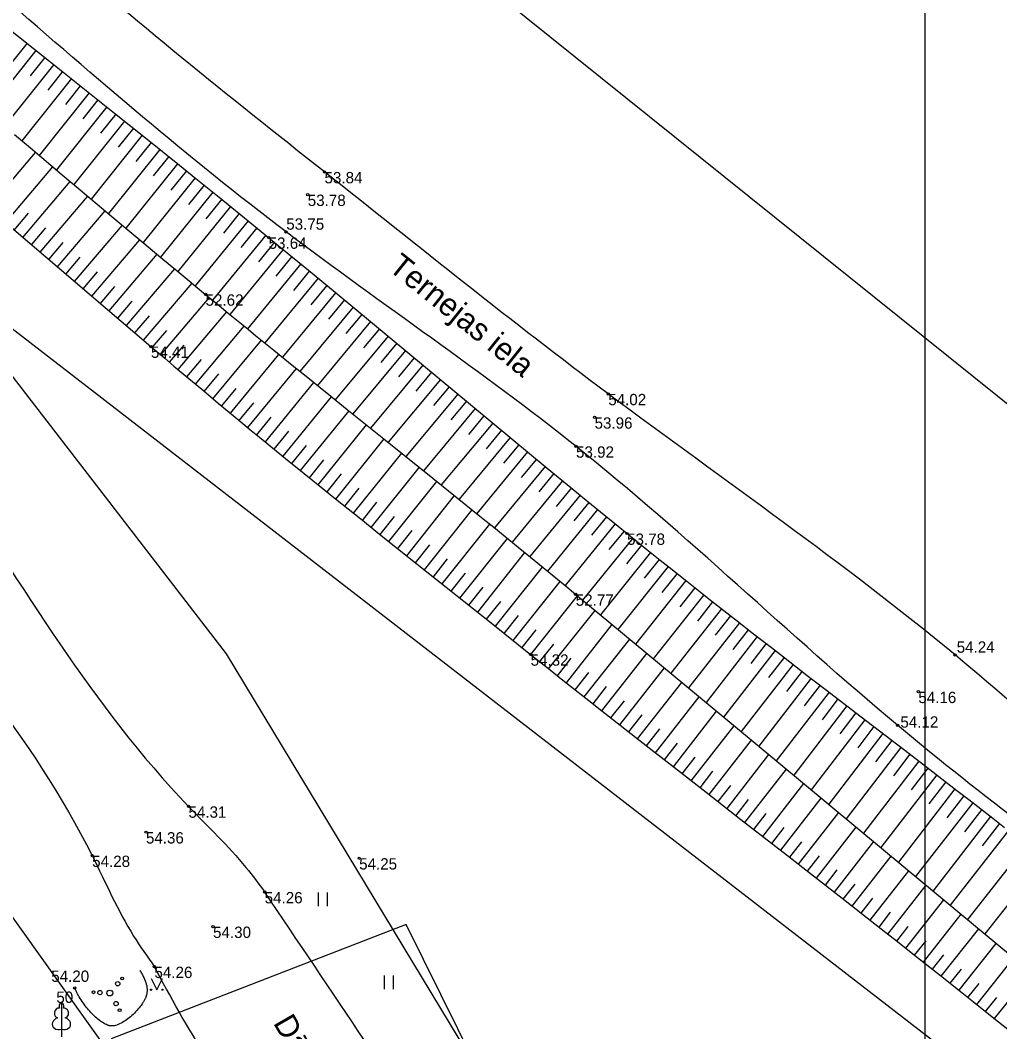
# Model space of a CAD drawing. Extents: x 578395 to 578590, y 418519 to 418816.
# Drawn here: x 578460.43 to 578503.64, y 418601.62 to 418646.22 of the extents above; entities that cross this region are included whole.
import ezdxf

# ---------------------------------------------------------------- set-up
doc = ezdxf.new("R2010")
doc.units = 0
for name, color, linetype in [('CELI_CMAL_####_####_#', 7, 'Continuous'), ('CELI_IELA_####_TKST_#', 7, 'Continuous'), ('ELEK_VADP_ZSPR_####_#', 7, 'Continuous'), ('RAMI_PLAN_####_TKST_#', 7, 'Continuous'), ('RELJ_AATZ_####_TKST_#', 7, 'Continuous'), ('RELJ_ELEM_####_####_#', 7, 'Continuous'), ('RELJ_NOGA_####_####_#', 7, 'Continuous'), ('RELJ_NOGL_####_####_#', 7, 'Continuous'), ('ROBZ_PROJ_####_####_#', 7, 'Continuous'), ('ROBZ_UZMR_####_####_#', 7, 'Continuous'), ('TERT_DIAM_####_TKST_#', 7, 'Continuous'), ('TERT_ELEM_####_####_#', 7, 'Continuous'), ('TERT_KONT_####_####_#', 7, 'Continuous')]:
    doc.layers.add(name, color=color, linetype=linetype)

msp = doc.modelspace()

# ---------------------------------------------------------------- linework, layer by layer
at = {"layer": 'CELI_CMAL_####_####_#'}
for points in [[(578540.02, 418586.371), (578525.988, 418597.847), (578512.594, 418608.642), (578501.669, 418618.235), (578486.368, 418629.744), (578473.85, 418639.529), (578461.404, 418649.849), (578445.482, 418664.308), (578434.891, 418671.618), (578433.593, 418673.245), (578433.709, 418674.571), (578434.344, 418682.513), (578433.832, 418698.668), (578431.508, 418715.146), (578429.961, 418730.384), (578428.634, 418741.31), (578426.857, 418755.172), (578424.464, 418771.373), (578422.35, 418787.381), (578420.601, 418802.682)], [(578422.643, 418673.344), (578426.408, 418667.598), (578432.023, 418657.972), (578440.378, 418642.229), (578453.358, 418623.699), (578463.599, 418609.382), (578465.428, 418605.837), (578466.347, 418604.486)], [(578433.603, 418667.727), (578433.533, 418667.219), (578433.834, 418664.827), (578435.716, 418660.389), (578444.472, 418644.493), (578457.112, 418626.41), (578467.85, 418611.554), (578470.384, 418608.861), (578471.211, 418607.779)], [(578538.092, 418583.58), (578523.866, 418595.463), (578510.65, 418606.122), (578499.131, 418615.129), (578484.947, 418627.43), (578472.156, 418636.888), (578459.663, 418647.262), (578443.345, 418661.302), (578436.955, 418666.057), (578434.564, 418667.369), (578433.603, 418667.727)], [(578494.854, 418568.017), (578493.222, 418570.924), (578490.763, 418575.52), (578488.331, 418580.13), (578485.806, 418584.688), (578479.899, 418594.609), (578471.211, 418607.779)], [(578473.294, 418588.796), (578474.34, 418590.351), (578474.316, 418591.662), (578471.816, 418595.464), (578470.23, 418598.144), (578468.612, 418600.561), (578466.347, 418604.486)]]:
    msp.add_spline(points, degree=3, dxfattribs=at)
at = {"layer": 'ELEK_VADP_ZSPR_####_#'}
msp.add_lwpolyline([(578485.065, 418590.965), (578477.452, 418606.345), (578464.439, 418601.302)], dxfattribs=at)
at = {"layer": 'RAMI_PLAN_####_TKST_#'}
msp.add_line((578500.351, 418519.111), (578500.351, 418667.611), dxfattribs=at)
at = {"layer": 'RELJ_ELEM_####_####_#'}
for centre in [(578473.85, 418639.529), (578473.111, 418638.53), (578472.156, 418636.888), (578471.386, 418636.641), (578468.603, 418634.132), (578466.192, 418631.832), (578486.368, 418629.744), (578485.765, 418628.71), (578484.947, 418627.43), (578487.2, 418623.587), (578484.935, 418620.902), (578482.943, 418618.258), (578501.669, 418618.235), (578500.049, 418616.61), (578499.131, 418615.129), (578467.85, 418611.554), (578465.971, 418610.418), (578463.599, 418609.382), (578475.378, 418609.27), (578471.211, 418607.779), (578468.934, 418606.253), (578466.347, 418604.486), (578462.833, 418603.546)]:
    msp.add_circle(centre, 0.05, dxfattribs=at)
at = {"layer": 'RELJ_NOGA_####_####_#'}
for p, q in [((578461.12, 418644.892), (578458.975, 418642.204)), ((578460.73, 418645.204), (578460.089, 418644.401)), ((578461.511, 418644.579), (578460.864, 418643.77)), ((578461.902, 418644.268), (578459.737, 418641.556)), ((578462.293, 418643.956), (578461.64, 418643.138)), ((578462.683, 418643.644), (578460.5, 418640.908)), ((578463.074, 418643.332), (578462.416, 418642.508)), ((578463.465, 418643.02), (578461.264, 418640.262)), ((578463.856, 418642.708), (578463.193, 418641.877)), ((578464.247, 418642.396), (578462.028, 418639.617)), ((578465.028, 418641.772), (578462.79, 418638.975)), ((578464.637, 418642.084), (578463.968, 418641.248)), ((578465.418, 418641.459), (578464.745, 418640.618)), ((578465.809, 418641.147), (578463.557, 418638.332)), ((578466.199, 418640.834), (578465.52, 418639.988)), ((578459.018, 418637.942), (578461.106, 418640.395)), ((578466.589, 418640.521), (578464.319, 418637.693)), ((578466.979, 418640.208), (578466.296, 418639.358)), ((578459.779, 418637.294), (578461.871, 418639.75)), ((578467.369, 418639.895), (578465.087, 418637.052)), ((578467.758, 418639.582), (578467.071, 418638.728)), ((578460.54, 418636.646), (578462.635, 418639.105)), ((578468.148, 418639.268), (578465.85, 418636.415)), ((578468.926, 418638.64), (578466.615, 418635.779)), ((578468.537, 418638.954), (578467.845, 418638.098)), ((578461.302, 418635.997), (578463.401, 418638.462)), ((578469.314, 418638.326), (578468.619, 418637.467)), ((578460.16, 418636.97), (578460.788, 418637.707)), ((578462.063, 418635.349), (578464.168, 418637.82)), ((578469.703, 418638.011), (578467.377, 418635.146)), ((578470.479, 418637.38), (578468.142, 418634.514)), ((578470.091, 418637.696), (578469.393, 418636.835)), ((578460.921, 418636.321), (578461.55, 418637.06)), ((578462.824, 418634.7), (578464.935, 418637.179)), ((578470.867, 418637.065), (578470.165, 418636.204)), ((578461.682, 418635.673), (578462.313, 418636.413)), ((578463.585, 418634.052), (578465.703, 418636.538)), ((578471.254, 418636.749), (578468.913, 418633.877)), ((578471.641, 418636.432), (578470.937, 418635.572)), ((578472.028, 418636.115), (578469.674, 418633.251)), ((578462.444, 418635.025), (578463.076, 418635.767)), ((578464.347, 418633.404), (578466.472, 418635.898)), ((578472.801, 418635.48), (578470.448, 418632.617)), ((578472.414, 418635.798), (578471.708, 418634.939)), ((578463.205, 418634.376), (578463.839, 418635.121)), ((578465.108, 418632.755), (578467.241, 418635.259)), ((578473.187, 418635.163), (578472.48, 418634.306)), ((578465.869, 418632.107), (578468.011, 418634.622)), ((578473.573, 418634.845), (578471.218, 418631.991)), ((578463.966, 418633.728), (578464.602, 418634.475)), ((578474.344, 418634.208), (578471.991, 418631.364)), ((578473.958, 418634.527), (578473.253, 418633.671)), ((578464.727, 418633.079), (578465.366, 418633.829)), ((578466.631, 418631.459), (578468.778, 418633.988)), ((578474.729, 418633.89), (578474.024, 418633.038)), ((578467.395, 418630.814), (578469.537, 418633.363)), ((578475.114, 418633.571), (578472.765, 418630.738)), ((578475.499, 418633.252), (578474.796, 418632.403)), ((578465.489, 418632.431), (578466.13, 418633.184)), ((578475.884, 418632.933), (578473.544, 418630.111)), ((578466.25, 418631.783), (578466.893, 418632.54)), ((578468.161, 418630.171), (578470.304, 418632.735)), ((578476.269, 418632.613), (578475.568, 418631.768)), ((578468.93, 418629.531), (578471.073, 418632.109)), ((578476.654, 418632.294), (578474.323, 418629.484)), ((578477.039, 418631.975), (578476.34, 418631.134)), ((578467.013, 418631.136), (578467.656, 418631.898)), ((578469.7, 418628.893), (578471.841, 418631.485)), ((578477.423, 418631.655), (578475.1, 418628.86)), ((578467.778, 418630.492), (578468.422, 418631.258)), ((578478.192, 418631.016), (578475.881, 418628.234)), ((578477.808, 418631.336), (578477.113, 418630.499)), ((578468.545, 418629.851), (578469.187, 418630.623)), ((578470.471, 418628.257), (578472.612, 418630.862)), ((578478.577, 418630.697), (578477.885, 418629.864)), ((578471.245, 418627.624), (578473.382, 418630.241)), ((578478.961, 418630.377), (578476.661, 418627.608)), ((578469.314, 418629.211), (578469.956, 418629.988)), ((578479.731, 418629.738), (578477.441, 418626.983)), ((578479.346, 418630.057), (578478.657, 418629.229)), ((578470.085, 418628.575), (578470.727, 418629.355)), ((578472.02, 418626.992), (578474.157, 418629.617)), ((578480.115, 418629.418), (578479.43, 418628.594)), ((578472.797, 418626.362), (578474.932, 418628.995)), ((578480.5, 418629.099), (578478.223, 418626.355)), ((578470.858, 418627.94), (578471.5, 418628.723)), ((578473.575, 418625.733), (578475.707, 418628.374)), ((578481.269, 418628.46), (578479.003, 418625.729)), ((578480.885, 418628.78), (578480.203, 418627.958)), ((578471.632, 418627.307), (578472.274, 418628.093)), ((578481.654, 418628.141), (578480.977, 418627.323)), ((578472.408, 418626.677), (578473.048, 418627.466)), ((578474.353, 418625.106), (578476.479, 418627.755)), ((578482.04, 418627.823), (578479.786, 418625.1)), ((578482.425, 418627.504), (578481.75, 418626.688)), ((578475.133, 418624.48), (578477.259, 418627.129)), ((578482.81, 418627.185), (578480.564, 418624.472)), ((578473.185, 418626.047), (578473.825, 418626.839)), ((578483.196, 418626.867), (578482.524, 418626.053)), ((578473.964, 418625.419), (578474.602, 418626.213)), ((578475.914, 418623.855), (578478.035, 418626.507)), ((578483.581, 418626.548), (578481.346, 418623.84)), ((578483.967, 418626.231), (578483.299, 418625.418)), ((578476.695, 418623.231), (578478.811, 418625.884)), ((578484.353, 418625.913), (578482.126, 418623.206)), ((578474.743, 418624.793), (578475.381, 418625.588)), ((578477.477, 418622.607), (578479.59, 418625.257)), ((578485.126, 418625.278), (578482.906, 418622.571)), ((578484.74, 418625.595), (578484.073, 418624.783)), ((578475.523, 418624.167), (578476.16, 418624.963)), ((578485.513, 418624.962), (578484.848, 418624.149)), ((578476.304, 418623.543), (578476.939, 418624.339)), ((578478.259, 418621.984), (578480.365, 418624.632)), ((578485.9, 418624.645), (578483.683, 418621.934)), ((578486.288, 418624.329), (578485.624, 418623.514)), ((578479.042, 418621.362), (578481.143, 418624.004)), ((578486.675, 418624.013), (578484.46, 418621.294)), ((578477.086, 418622.919), (578477.72, 418623.715)), ((578487.063, 418623.698), (578486.399, 418622.88)), ((578477.868, 418622.296), (578478.501, 418623.09)), ((578479.825, 418620.74), (578481.92, 418623.374)), ((578487.452, 418623.383), (578485.238, 418620.651)), ((578487.841, 418623.069), (578487.177, 418622.246)), ((578480.607, 418620.117), (578482.695, 418622.743)), ((578488.23, 418622.756), (578486.021, 418620.002)), ((578478.651, 418621.673), (578479.282, 418622.467)), ((578481.39, 418619.495), (578483.471, 418622.108)), ((578489.011, 418622.131), (578486.797, 418619.359)), ((578488.62, 418622.443), (578487.956, 418621.615)), ((578479.433, 418621.051), (578480.063, 418621.842)), ((578489.402, 418621.819), (578488.738, 418620.984)), ((578480.216, 418620.428), (578480.844, 418621.217)), ((578482.172, 418618.872), (578484.244, 418621.473)), ((578489.794, 418621.508), (578487.573, 418618.715)), ((578482.955, 418618.249), (578485.014, 418620.837)), ((578490.578, 418620.888), (578488.355, 418618.067)), ((578490.186, 418621.198), (578489.52, 418620.356)), ((578480.999, 418619.806), (578481.624, 418620.592)), ((578490.971, 418620.579), (578490.303, 418619.728)), ((578481.781, 418619.183), (578482.404, 418619.965)), ((578483.737, 418617.626), (578485.784, 418620.198)), ((578491.365, 418620.27), (578489.13, 418617.424)), ((578491.758, 418619.962), (578491.087, 418619.104)), ((578484.521, 418617.005), (578486.545, 418619.568)), ((578492.152, 418619.654), (578489.91, 418616.777)), ((578482.563, 418618.56), (578483.183, 418619.339)), ((578492.941, 418619.04), (578490.685, 418616.134)), ((578492.547, 418619.347), (578491.871, 418618.48)), ((578483.346, 418617.937), (578483.962, 418618.711)), ((578485.305, 418616.385), (578487.315, 418618.929)), ((578493.336, 418618.733), (578492.656, 418617.858)), ((578484.129, 418617.315), (578484.739, 418618.086)), ((578486.091, 418615.766), (578488.077, 418618.297)), ((578493.731, 418618.427), (578491.459, 418615.492)), ((578494.127, 418618.121), (578493.443, 418617.235)), ((578486.878, 418615.149), (578488.847, 418617.659)), ((578494.522, 418617.815), (578492.233, 418614.85)), ((578484.913, 418616.695), (578485.518, 418617.461)), ((578495.314, 418617.204), (578493.007, 418614.208)), ((578494.918, 418617.51), (578494.228, 418616.616)), ((578485.698, 418616.076), (578486.297, 418616.837)), ((578487.665, 418614.532), (578489.613, 418617.023)), ((578495.71, 418616.899), (578495.015, 418615.996)), ((578488.453, 418613.916), (578490.381, 418616.387)), ((578496.107, 418616.594), (578493.781, 418613.567)), ((578486.484, 418615.458), (578487.078, 418616.214)), ((578496.9, 418615.985), (578494.551, 418612.928)), ((578496.503, 418616.29), (578495.802, 418615.377)), ((578487.271, 418614.84), (578487.858, 418615.591)), ((578489.241, 418613.301), (578491.148, 418615.75)), ((578497.296, 418615.681), (578496.588, 418614.759)), ((578488.059, 418614.224), (578488.641, 418614.968)), ((578490.03, 418612.687), (578491.918, 418615.112)), ((578497.693, 418615.376), (578495.322, 418612.288)), ((578498.089, 418615.072), (578497.375, 418614.141)), ((578498.486, 418614.767), (578496.093, 418611.649)), ((578488.847, 418613.609), (578489.422, 418614.346)), ((578490.819, 418612.073), (578492.687, 418614.475)), ((578499.279, 418614.158), (578496.863, 418611.01)), ((578498.883, 418614.463), (578498.161, 418613.523)), ((578489.636, 418612.994), (578490.205, 418613.725)), ((578491.609, 418611.459), (578493.457, 418613.836)), ((578499.676, 418613.854), (578498.947, 418612.905)), ((578492.398, 418610.845), (578494.226, 418613.197)), ((578500.072, 418613.549), (578497.631, 418610.373)), ((578500.469, 418613.244), (578499.733, 418612.287)), ((578490.425, 418612.38), (578490.988, 418613.104)), ((578500.865, 418612.94), (578498.397, 418609.737)), ((578491.214, 418611.766), (578491.771, 418612.483)), ((578493.188, 418610.231), (578494.996, 418612.558)), ((578501.657, 418612.329), (578499.167, 418609.098)), ((578501.261, 418612.634), (578500.517, 418611.669)), ((578492.004, 418611.152), (578492.555, 418611.861)), ((578493.977, 418609.618), (578495.767, 418611.92)), ((578502.053, 418612.024), (578501.302, 418611.051)), ((578502.448, 418611.718), (578499.929, 418608.466)), ((578502.844, 418611.412), (578502.085, 418610.432)), ((578492.793, 418610.538), (578493.339, 418611.24)), ((578494.767, 418609.004), (578496.538, 418611.28)), ((578503.239, 418611.105), (578500.7, 418607.827)), ((578493.583, 418609.925), (578494.122, 418610.619)), ((578495.556, 418608.389), (578497.31, 418610.639)), ((578503.634, 418610.799), (578502.867, 418609.813)), ((578504.028, 418610.491), (578501.459, 418607.198)), ((578494.372, 418609.311), (578494.906, 418609.997)), ((578496.344, 418607.774), (578498.08, 418610)), ((578504.816, 418609.876), (578502.222, 418606.565)), ((578495.161, 418608.697), (578495.69, 418609.376)), ((578497.132, 418607.159), (578498.853, 418609.359)), ((578505.603, 418609.259), (578502.986, 418605.931)), ((578495.95, 418608.082), (578496.473, 418608.753)), ((578497.92, 418606.543), (578499.625, 418608.718)), ((578496.739, 418607.467), (578497.256, 418608.131)), ((578498.707, 418605.926), (578500.398, 418608.078)), ((578497.526, 418606.851), (578498.04, 418607.508)), ((578499.493, 418605.307), (578501.17, 418607.437)), ((578498.313, 418606.234), (578498.823, 418606.884)), ((578500.278, 418604.688), (578501.944, 418606.795)), ((578499.1, 418605.617), (578499.605, 418606.259)), ((578501.062, 418604.067), (578502.719, 418606.152)), ((578499.886, 418604.998), (578500.388, 418605.633)), ((578501.845, 418603.445), (578503.489, 418605.514)), ((578500.67, 418604.378), (578501.168, 418605.007)), ((578502.627, 418602.822), (578504.267, 418604.87)), ((578501.454, 418603.756), (578501.949, 418604.379)), ((578503.407, 418602.196), (578505.042, 418604.228)), ((578502.236, 418603.134), (578502.729, 418603.751)), ((578503.017, 418602.509), (578503.508, 418603.122))]:
    msp.add_line(p, q, dxfattribs=at)
for points in [[(578459.56, 418646.138), (578461.714, 418644.417), (578464.588, 418642.123), (578466.024, 418640.975), (578467.458, 418639.824), (578468.174, 418639.247), (578469.128, 418638.477), (578469.604, 418638.092), (578470.317, 418637.512), (578471.386, 418636.641), (578471.974, 418636.16), (578473.147, 418635.196), (578474.319, 418634.229), (578475.099, 418633.584), (578476.658, 418632.291), (578478.216, 418630.997), (578480.293, 418629.271), (578481.332, 418628.408), (578482.892, 418627.117), (578483.673, 418626.473), (578484.716, 418625.615), (578485.238, 418625.187), (578486.022, 418624.546), (578486.807, 418623.906), (578487.2, 418623.587), (578487.491, 418623.351), (578488.074, 418622.881), (578488.658, 418622.412), (578489.049, 418622.101), (578489.831, 418621.479), (578490.418, 418621.014), (578490.81, 418620.705), (578491.596, 418620.089), (578491.99, 418619.781), (578492.777, 418619.167), (578493.567, 418618.554), (578493.567, 418618.554), (578494.093, 418618.147), (578495.147, 418617.333), (578495.939, 418616.723), (578497.523, 418615.506), (578499.637, 418613.884), (578500.693, 418613.072), (578501.748, 418612.259), (578502.275, 418611.852), (578503.328, 418611.036), (578503.854, 418610.628)], [(578452.166, 418643.778), (578466.192, 418631.832), (578466.801, 418631.315), (578467.207, 418630.972), (578468.022, 418630.287), (578468.431, 418629.945), (578469.25, 418629.265), (578470.07, 418628.587), (578470.619, 418628.136), (578470.985, 418627.836), (578471.718, 418627.238), (578472.131, 418626.902), (578472.958, 418626.231), (578473.786, 418625.562), (578474.339, 418625.117), (578475.447, 418624.228), (578476.278, 418623.563), (578477.943, 418622.236), (578481.277, 418619.585), (578482.943, 418618.258), (578483.799, 418617.577), (578484.37, 418617.124), (578485.515, 418616.22), (578486.088, 418615.769), (578487.236, 418614.868), (578488.385, 418613.969), (578489.151, 418613.371), (578490.686, 418612.176), (578492.221, 418610.983), (578494.269, 418609.391), (578495.292, 418608.595), (578496.826, 418607.399), (578497.592, 418606.8), (578498.612, 418606), (578499.122, 418605.6), (578499.886, 418604.998), (578501.03, 418604.093), (578502.044, 418603.287), (578502.551, 418602.882), (578503.31, 418602.275), (578504.068, 418601.665)]]:
    msp.add_lwpolyline(points, dxfattribs=at)
at = {"layer": 'RELJ_NOGL_####_####_#'}
msp.add_lwpolyline([(578460.18, 418641.179), (578460.879, 418640.587), (578462.277, 418639.407), (578462.978, 418638.817), (578464.38, 418637.642), (578465.785, 418636.469), (578466.724, 418635.689), (578467.35, 418635.169), (578468.603, 418634.132), (578469.204, 418633.637), (578469.605, 418633.307), (578470.408, 418632.65), (578470.81, 418632.322), (578471.616, 418631.668), (578472.423, 418631.015), (578472.961, 418630.58), (578474.039, 418629.712), (578474.848, 418629.062), (578476.468, 418627.763), (578478.627, 418626.031), (578479.706, 418625.164), (578480.783, 418624.295), (578481.321, 418623.86), (578482.395, 418622.988), (578482.931, 418622.55), (578483.734, 418621.893), (578484.535, 418621.233), (578484.935, 418620.902), (578487.516, 418618.763), (578492.677, 418614.483), (578499.557, 418608.775), (578502.997, 418605.922), (578508.16, 418601.644)], dxfattribs=at)
at = {"layer": 'ROBZ_PROJ_####_####_#'}
msp.add_line((578456.044, 418635.726), (578533.748, 418575.711), dxfattribs=at)
at = {"layer": 'ROBZ_UZMR_####_####_#'}
for p, q in [((578505.878, 418627.76), (578479.129, 418649.244)), ((578468.202, 418595.33), (578437, 418638.94)), ((578456.044, 418635.726), (578469.515, 418618.285)), ((578469.515, 418618.285), (578506.631, 418556.899))]:
    msp.add_line(p, q, dxfattribs=at)
at = {"layer": 'TERT_ELEM_####_####_#'}
for p, q in [((578473.578, 418607.152), (578473.578, 418607.752)), ((578473.978, 418607.152), (578473.978, 418607.752)), ((578466.2, 418603.97), (578466.45, 418603.47)), ((578466.45, 418603.47), (578466.7, 418603.97)), ((578476.5, 418603.5), (578476.5, 418604.1)), ((578476.9, 418603.5), (578476.9, 418604.1)), ((578462.244, 418601.736), (578462.244, 418601.389))]:
    msp.add_line(p, q, dxfattribs=at)
for points in [[(578462.244, 418602.889), (578462.244, 418601.736)], [(578462.334, 418602.657), (578462.333, 418602.658)]]:
    msp.add_lwpolyline(points, dxfattribs=at)
for centre, radius in [((578464.725, 418603.733), 0.096), ((578464.921, 418603.965), 0.064), ((578463.659, 418603.36), 0.064), ((578463.943, 418603.346), 0.096), ((578464.377, 418603.325), 0.128), ((578466.2, 418603.47), 0.028), ((578466.7, 418603.47), 0.0263), ((578464.654, 418602.859), 0.096), ((578464.811, 418602.569), 0.064)]:
    msp.add_circle(centre, radius, dxfattribs=at)
for centre, major_axis, ratio, start_param, end_param in [((578462.116, 418602.444), (-0.039, -0.212), 0.861323, 3.141593, 6.283185), ((578462.244, 418602.739), (0, -0.15), 0.707107, 3.14537, 5.287485), ((578462.244, 418602.739), (0, -0.15), 0.707107, 0.995701, 3.137816), ((578462.372, 418602.444), (0.039, -0.212), 0.861323, 0, 3.141593), ((578462.154, 418601.982), (0.307, 0.095), 0.814445, 1.570796, 4.752015), ((578462.334, 418601.982), (-0.307, 0.095), 0.814445, 1.531171, 4.712389)]:
    msp.add_ellipse(centre, major_axis=major_axis, ratio=ratio, start_param=start_param, end_param=end_param, dxfattribs=at)
at = {"layer": 'TERT_KONT_####_####_#'}
msp.add_spline([(578465.702, 418604.313), (578465.793, 418604.164), (578465.873, 418604.013), (578465.987, 418603.712), (578466.024, 418603.417), (578466.007, 418603.274), (578465.989, 418603.203), (578465.977, 418603.168), (578465.971, 418603.151), (578465.964, 418603.134), (578465.91, 418603.02), (578465.842, 418602.903), (578465.67, 418602.666), (578465.229, 418602.23), (578464.746, 418601.935), (578464.521, 418601.875), (578464.418, 418601.873), (578464.37, 418601.879), (578464.347, 418601.884), (578464.324, 418601.891), (578464.225, 418601.93), (578463.913, 418602.125), (578463.49, 418602.524), (578463.112, 418603.021), (578462.956, 418603.284), (578462.89, 418603.416), (578462.833, 418603.546)], degree=3, dxfattribs=at)

# ---------------------------------------------------------------- texts
at = {"layer": 'CELI_IELA_####_TKST_#'}
for s, rotation, p in [('Ternejas iela', 321.2296, (578476.622, 418635.232)), ('Dārza iela', 299.988, (578471.568, 418602.009))]:
    msp.add_text(s, height=1, rotation=rotation, dxfattribs=at).set_placement(p)
at = {"layer": 'RELJ_AATZ_####_TKST_#'}
for s, p in [('53.84', (578473.85, 418639.029)), ('53.78', (578473.111, 418638.03)), ('53.75', (578472.162, 418636.984)), ('53.64', (578471.386, 418636.141)), ('52.62', (578468.603, 418633.632)), ('54.41', (578466.192, 418631.332)), ('54.02', (578486.368, 418629.244)), ('53.96', (578485.765, 418628.21)), ('53.92', (578484.947, 418626.93)), ('53.78', (578487.2, 418623.087)), ('52.77', (578484.935, 418620.402)), ('54.24', (578501.741, 418618.331)), ('54.32', (578482.943, 418617.758)), ('54.16', (578500.049, 418616.11)), ('54.12', (578499.257, 418615.027)), ('54.31', (578467.85, 418611.054)), ('54.36', (578465.971, 418609.918)), ('54.28', (578463.599, 418608.882)), ('54.25', (578475.378, 418608.77)), ('54.26', (578471.211, 418607.279)), ('54.30', (578468.934, 418605.753)), ('54.20', (578461.794, 418603.817)), ('54.26', (578466.347, 418603.986))]:
    msp.add_text(s, height=0.5, dxfattribs=at).set_placement(p)
at = {"layer": 'TERT_DIAM_####_TKST_#'}
msp.add_text('50', height=0.5, dxfattribs=at).set_placement((578462.019, 418602.889))

doc.saveas('drawing.dxf')
